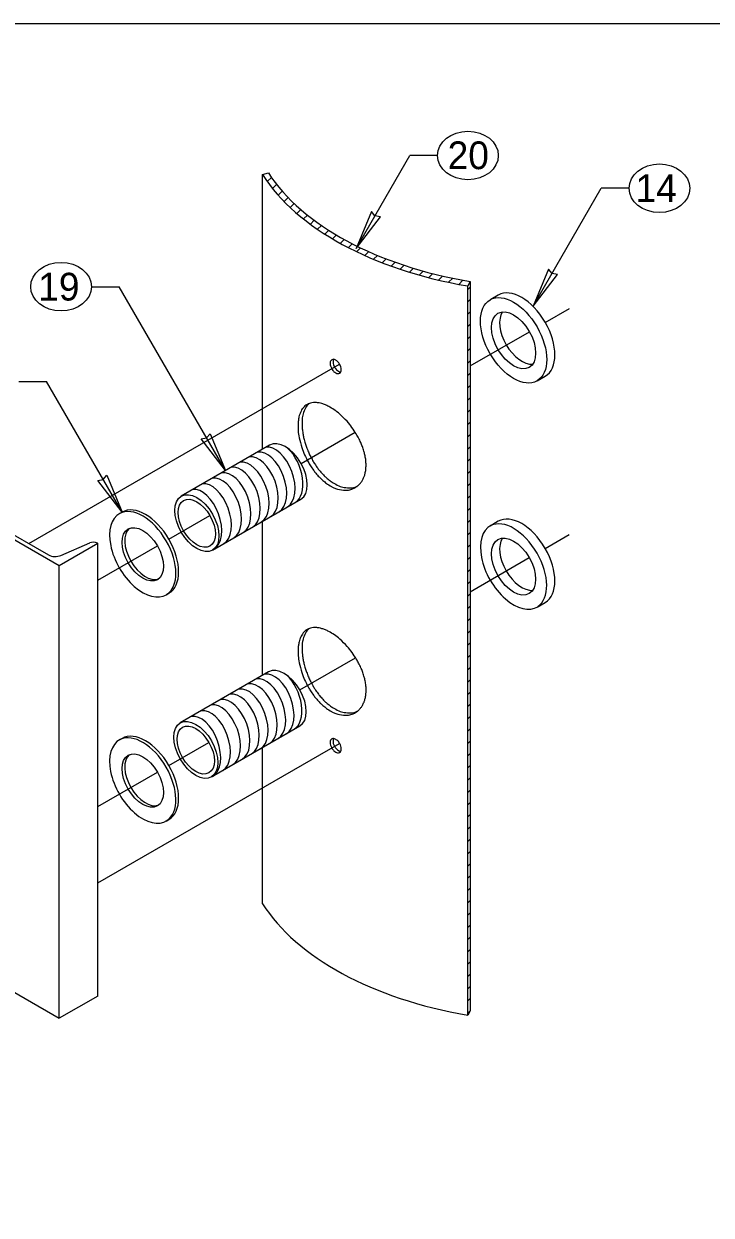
# Model space of a CAD drawing. Extents: x 99862 to 104211, y 98939 to 102076.
# Drawn here: x 102294 to 102690, y 101389 to 102076 of the extents above; entities that cross this region are included whole.
import ezdxf

# ---------------------------------------------------------------- set-up
doc = ezdxf.new("R2010")
doc.units = 0
for name, color, linetype in [('Level 1', 7, 'Continuous'), ('Level 14', 7, 'Continuous'), ('Level 15', 7, 'Continuous'), ('Level 17', 7, 'Continuous'), ('Level 18', 7, 'Continuous'), ('Level 19', 7, 'Continuous'), ('Level 20', 7, 'Continuous')]:
    doc.layers.add(name, color=color, linetype=linetype)

msp = doc.modelspace()

# ---------------------------------------------------------------- linework, layer by layer
at = {"layer": 'Level 1'}
for p, q in [((102431.79, 101988.6), (102435.1, 101989.56)), ((102431.79, 101830.29), (102431.79, 101988.6)), ((102434.49, 101984.6), (102436.85, 101986.97)), ((102437.53, 101980.57), (102439.88, 101982.92)), ((102440.77, 101976.74), (102443.09, 101979.06)), ((102444.17, 101973.08), (102446.48, 101975.38)), ((102447.74, 101969.57), (102450.03, 101971.86)), ((102451.45, 101966.21), (102453.73, 101968.49)), ((102455.31, 101963), (102457.58, 101965.27)), ((102459.33, 101959.95), (102461.59, 101962.21)), ((102463.47, 101957.02), (102465.73, 101959.27)), ((102467.73, 101954.2), (102469.98, 101956.46)), ((102472.09, 101951.49), (102474.34, 101953.75)), ((102476.6, 101948.94), (102478.85, 101951.18)), ((102481.22, 101946.48), (102483.47, 101948.73)), ((102485.94, 101944.13), (102488.19, 101946.38)), ((102490.75, 101941.87), (102493.02, 101944.14)), ((102495.71, 101939.76), (102497.96, 101942.01)), ((102500.76, 101937.73), (102503.02, 101940)), ((102505.89, 101935.8), (102508.18, 101938.09)), ((102511.15, 101933.98), (102513.43, 101936.26)), ((102516.52, 101932.28), (102518.8, 101934.57)), ((102521.98, 101930.67), (102524.29, 101932.98)), ((102527.52, 101929.15), (102529.86, 101931.48)), ((102533.21, 101927.76), (102535.53, 101930.08)), ((102539, 101926.48), (102541.34, 101928.82)), ((102544.88, 101925.29), (102547.26, 101927.67)), ((102551.32, 101926.91), (102549.99, 101924.35)), ((102549.99, 101503.94), (102549.99, 101924.35)), ((102550, 101922.26), (102551.32, 101923.58)), ((102551.32, 101926.91), (102551.32, 101506.5)), ((102550, 101915.19), (102551.32, 101916.51)), ((102550, 101908.12), (102551.32, 101909.44)), ((102550, 101901.05), (102551.32, 101902.37)), ((102550, 101893.98), (102551.32, 101895.3)), ((102471.72, 101881.84), (102471.67, 101881.81)), ((102550, 101886.91), (102551.32, 101888.23)), ((102550, 101879.84), (102551.32, 101881.16)), ((102550, 101872.77), (102551.32, 101874.09)), ((102550, 101865.69), (102551.32, 101867.02)), ((102550, 101858.62), (102551.32, 101859.94)), ((102550, 101851.55), (102551.32, 101852.87)), ((102550, 101844.48), (102551.32, 101845.8)), ((102550, 101837.41), (102551.32, 101838.73)), ((102550, 101830.34), (102551.32, 101831.66)), ((102550, 101823.27), (102551.32, 101824.59)), ((102550, 101816.2), (102551.32, 101817.52)), ((102550, 101809.13), (102551.32, 101810.45)), ((102550, 101802.05), (102551.32, 101803.38)), ((102550, 101794.98), (102551.32, 101796.3)), ((102431.79, 101699.85), (102431.79, 101788.72)), ((102550, 101787.91), (102551.32, 101789.23)), ((102550, 101780.84), (102551.32, 101782.16)), ((102550, 101773.77), (102551.32, 101775.09)), ((102550, 101766.7), (102551.32, 101768.02)), ((102550, 101759.63), (102551.32, 101760.95)), ((102550, 101752.56), (102551.32, 101753.88)), ((102550, 101745.49), (102551.32, 101746.81)), ((102550, 101738.41), (102551.32, 101739.74)), ((102550, 101731.34), (102551.32, 101732.67)), ((102550, 101724.27), (102551.32, 101725.59)), ((102550, 101717.2), (102551.32, 101718.52)), ((102550, 101710.13), (102551.32, 101711.45)), ((102550, 101703.06), (102551.32, 101704.38)), ((102550, 101695.99), (102551.32, 101697.31)), ((102550, 101688.92), (102551.32, 101690.24)), ((102550, 101681.84), (102551.32, 101683.17)), ((102550, 101674.77), (102551.32, 101676.1)), ((102550, 101667.7), (102551.32, 101669.03)), ((102471.72, 101663.22), (102471.67, 101663.19)), ((102550, 101660.63), (102551.32, 101661.95)), ((102431.79, 101568.19), (102431.79, 101658.28)), ((102550, 101653.56), (102551.32, 101654.88)), ((102550, 101646.49), (102551.32, 101647.81)), ((102550, 101639.42), (102551.32, 101640.74)), ((102550, 101632.35), (102551.32, 101633.67)), ((102550, 101625.28), (102551.32, 101626.6)), ((102550, 101618.2), (102551.32, 101619.53)), ((102550, 101611.13), (102551.32, 101612.46)), ((102550, 101604.06), (102551.32, 101605.39)), ((102550, 101596.99), (102551.32, 101598.32)), ((102550, 101589.92), (102551.32, 101591.24)), ((102550, 101582.85), (102551.32, 101584.17)), ((102550, 101575.78), (102551.32, 101577.1)), ((102550, 101568.71), (102551.32, 101570.03)), ((102550, 101561.64), (102551.32, 101562.96)), ((102550, 101554.56), (102551.32, 101555.89)), ((102550, 101547.49), (102551.32, 101548.82)), ((102550, 101540.42), (102551.32, 101541.75)), ((102550, 101533.35), (102551.32, 101534.68)), ((102550, 101526.28), (102551.32, 101527.6)), ((102550, 101519.21), (102551.32, 101520.53)), ((102550, 101512.14), (102551.32, 101513.46)), ((102551.32, 101506.5), (102549.99, 101503.94)), ((102550, 101505.07), (102551.2, 101506.27))]:
    msp.add_line(p, q, dxfattribs=at)
msp.add_lwpolyline([(99862, 99999.5), (103151, 99999.5), (103151, 102075.5), (99862, 102075.5)], close=True, dxfattribs=at)
for centre, major_axis, ratio, start_param, end_param in [((102601.02, 102024.01), (180, 0), 0.57735, 3.489276, 4.425024), ((102601.7, 102025.33), (177.75, 0), 0.57735, 3.497642, 4.425024), ((102429.21, 101808.21), (-6.25, 17.28), 0.565545, 3.242095, 6.183178), ((102434.09, 101811.03), (-6.25, 17.28), 0.565545, 3.242095, 6.183178), ((102438.88, 101813.8), (-6.25, 17.28), 0.565545, 3.242095, 6.183178), ((102443.4, 101816.41), (-6.25, 17.28), 0.565545, 3.242095, 5.457347), ((102418.82, 101802.22), (-6.25, 17.28), 0.565545, 3.242095, 6.183178), ((102423.93, 101805.17), (-6.25, 17.28), 0.565545, 3.242095, 6.183178), ((102408.03, 101795.99), (-6.25, 17.28), 0.565545, 3.242095, 6.183178), ((102413.44, 101799.11), (-6.25, 17.28), 0.565545, 3.242095, 6.183178), ((102396.63, 101789.41), (-6.25, 17.28), 0.565545, 3.242095, 6.183178), ((102402.22, 101792.63), (-6.25, 17.28), 0.565545, 3.242095, 6.183178), ((102433.5, 101680.25), (-6.25, 17.28), 0.565545, 3.242095, 6.183178), ((102438.29, 101683.02), (-6.25, 17.28), 0.565545, 3.242095, 6.183178), ((102442.81, 101685.63), (-6.25, 17.28), 0.565545, 3.242095, 5.457347), ((102418.24, 101671.44), (-6.25, 17.28), 0.565545, 3.242095, 6.183178), ((102423.34, 101674.39), (-6.25, 17.28), 0.565545, 3.242095, 6.183178), ((102428.62, 101677.44), (-6.25, 17.28), 0.565545, 3.242095, 6.183178), ((102407.45, 101665.21), (-6.25, 17.28), 0.565545, 3.242095, 6.183178), ((102412.85, 101668.33), (-6.25, 17.28), 0.565545, 3.242095, 6.183178), ((102396.04, 101658.63), (-6.25, 17.28), 0.565545, 3.242095, 6.183178), ((102401.63, 101661.85), (-6.25, 17.28), 0.565545, 3.242095, 6.183178), ((102601.02, 101603.6), (-180, 0), 0.57735, 0.347684, 1.283395)]:
    msp.add_ellipse(centre, major_axis=major_axis, ratio=ratio, start_param=start_param, end_param=end_param, dxfattribs=at)
for points, degree in [([(102473.9, 101874.23), (102473.06, 101874.71), (102472.24, 101875.59), (102471.09, 101877.64), (102470.75, 101878.8), (102470.75, 101880.72), (102471.08, 101881.47), (102472.25, 101882.15), (102473.07, 101882.06), (102474.73, 101881.1), (102475.57, 101880.23), (102476.77, 101878.21), (102477.12, 101877.07), (102477.13, 101875.13), (102476.77, 101874.37), (102475.57, 101873.67), (102474.74, 101873.74), (102473.9, 101874.23)], 3), ([(102472.61, 101882.01), (102472.42, 101881.6), (102472.32, 101881.08), (102472.39, 101879.51), (102472.76, 101878.36), (102473.98, 101876.32), (102474.82, 101875.49), (102476.05, 101874.85), (102476.45, 101874.74), (102476.83, 101874.73)], 3), ([(102470.75, 101809.17), (102469.46, 101809.92), (102468.2, 101810.8), (102465.74, 101812.85), (102464.54, 101814.03), (102462.26, 101816.58), (102461.2, 101817.96), (102459.19, 101820.9), (102458.25, 101822.47), (102455.75, 101827.27), (102454.42, 101830.71), (102452.66, 101837.39), (102452.2, 101840.69), (102452.2, 101845.12), (102452.32, 101846.53), (102452.76, 101849.11), (102453.1, 101850.29), (102453.98, 101852.4), (102454.54, 101853.34), (102455.83, 101854.9), (102456.57, 101855.53), (102458.26, 101856.51), (102459.18, 101856.84), (102461.18, 101857.18), (102462.26, 101857.19), (102464.54, 101856.9), (102465.72, 101856.61), (102468.18, 101855.71), (102469.47, 101855.1), (102473.31, 101852.89), (102475.94, 101850.85), (102480.85, 101845.99), (102483.17, 101843.13), (102486.09, 101838.56), (102486.98, 101836.97), (102488.53, 101833.77), (102489.19, 101832.16), (102490.28, 101828.91), (102490.69, 101827.28), (102491.25, 101824.13), (102491.39, 101822.6), (102491.39, 101819.61), (102491.25, 101818.2), (102490.7, 101815.57), (102490.29, 101814.33), (102489.21, 101812.1), (102488.55, 101811.12), (102487.01, 101809.4), (102486.11, 101808.68), (102483.2, 101806.99), (102480.88, 101806.49), (102475.98, 101806.83), (102473.34, 101807.68), (102470.75, 101809.17)], 3), ([(102458.64, 101856.59), (102457.43, 101855.6), (102456.46, 101854.21), (102454.92, 101850.37), (102454.49, 101847.7), (102454.53, 101843.25), (102454.66, 101841.66), (102455.13, 101838.43), (102455.48, 101836.78), (102456.39, 101833.42), (102456.95, 101831.71), (102458.27, 101828.38), (102459.02, 101826.74), (102460.73, 101823.5), (102461.66, 101821.97), (102463.67, 101819.06), (102464.77, 101817.67), (102467.06, 101815.14), (102468.25, 101814), (102470.71, 101811.98), (102472, 101811.09), (102475.84, 101808.93), (102478.48, 101808.11), (102482.82, 101807.87), (102484.63, 101808.17), (102486.24, 101808.85)], 3), ([(102470.79, 101679.42), (102469.5, 101680.16), (102468.24, 101681.05), (102465.78, 101683.1), (102464.58, 101684.27), (102462.3, 101686.83), (102461.23, 101688.2), (102459.23, 101691.14), (102458.29, 101692.72), (102455.79, 101697.52), (102454.46, 101700.96), (102452.7, 101707.63), (102452.24, 101710.94), (102452.24, 101715.36), (102452.35, 101716.78), (102452.8, 101719.36), (102453.13, 101720.53), (102454.02, 101722.65), (102454.57, 101723.58), (102455.87, 101725.14), (102456.61, 101725.78), (102458.3, 101726.76), (102459.22, 101727.08), (102461.22, 101727.42), (102462.3, 101727.44), (102464.58, 101727.15), (102465.76, 101726.85), (102468.22, 101725.96), (102469.51, 101725.35), (102473.35, 101723.14), (102475.98, 101721.09), (102480.89, 101716.24), (102483.21, 101713.38), (102486.13, 101708.81), (102487.02, 101707.21), (102488.57, 101704.01), (102489.23, 101702.4), (102490.32, 101699.16), (102490.73, 101697.52), (102491.29, 101694.38), (102491.43, 101692.84), (102491.43, 101689.86), (102491.29, 101688.45), (102490.74, 101685.82), (102490.33, 101684.58), (102489.25, 101682.35), (102488.59, 101681.36), (102487.04, 101679.65), (102486.15, 101678.92), (102483.24, 101677.24), (102480.92, 101676.73), (102476.01, 101677.08), (102473.38, 101677.92), (102470.79, 101679.42)], 3), ([(102458.67, 101726.84), (102457.47, 101725.84), (102456.5, 101724.45), (102454.96, 101720.62), (102454.53, 101717.95), (102454.57, 101713.49), (102454.7, 101711.91), (102455.17, 101708.68), (102455.52, 101707.03), (102456.43, 101703.67), (102456.99, 101701.96), (102458.31, 101698.62), (102459.06, 101696.98), (102460.77, 101693.75), (102461.7, 101692.22), (102463.71, 101689.3), (102464.81, 101687.91), (102467.1, 101685.38), (102468.28, 101684.25), (102470.75, 101682.22), (102472.04, 101681.33), (102475.88, 101679.18), (102478.52, 101678.36), (102482.86, 101678.12), (102484.67, 101678.42), (102486.28, 101679.1)], 3), ([(102473.9, 101655.61), (102473.06, 101656.1), (102472.24, 101656.98), (102471.09, 101659.02), (102470.75, 101660.18), (102470.75, 101662.1), (102471.08, 101662.86), (102472.25, 101663.53), (102473.07, 101663.44), (102474.73, 101662.48), (102475.57, 101661.61), (102476.77, 101659.59), (102477.12, 101658.45), (102477.13, 101656.51), (102476.77, 101655.75), (102475.57, 101655.06), (102474.74, 101655.13), (102473.9, 101655.61)], 3), ([(102472.61, 101663.39), (102472.44, 101663.03), (102472.34, 101662.58), (102472.34, 101661.1), (102472.68, 101659.94), (102473.83, 101657.9), (102474.65, 101657.02), (102475.49, 101656.53)], 3), ([(102475.49, 101656.53), (102475.95, 101656.27), (102476.41, 101656.13), (102476.82, 101656.11)], 2)]:
    msp.add_open_spline(points, degree=degree, dxfattribs=at)
at = {"layer": 'Level 14'}
for p, q in [((102563.3, 101916.61), (102562.91, 101916.38)), ((102567.59, 101919.08), (102563.3, 101916.61)), ((102589.91, 101869.61), (102594.59, 101872.32)), ((102567.59, 101788.65), (102562.91, 101785.94)), ((102589.91, 101739.18), (102594.59, 101741.88))]:
    msp.add_line(p, q, dxfattribs=at)
for centre, major_axis, start_param, end_param in [((102581.09, 101895.7), (-13.5, 23.38), 3.141593, 6.283185), ((102581.09, 101895.7), (9, -15.59), 3.404941, 4.713019), ((102581.09, 101895.7), (9, -15.59), 4.713019, 6.019837), ((102576.41, 101762.56), (-13.5, 23.38), 6.251087, 9.456261), ((102576.41, 101762.56), (-13.5, 23.38), 3.175146, 6.249339), ((102581.09, 101765.27), (-13.5, 23.38), 3.141593, 6.283185), ((102581.09, 101765.27), (9, -15.59), 3.404941, 4.712389), ((102581.09, 101765.27), (9, -15.59), 4.712389, 6.019837)]:
    msp.add_ellipse(centre, major_axis=major_axis, ratio=0.57735, start_param=start_param, end_param=end_param, dxfattribs=at)
for centre, major_axis in [((102576.41, 101893), (-13.5, 23.38)), ((102576.41, 101893), (9, -15.59)), ((102576.41, 101762.56), (9, -15.59))]:
    msp.add_ellipse(centre, major_axis=major_axis, ratio=0.57735, dxfattribs=at)
at = {"layer": 'Level 15'}
for p, q in [((102485.64, 101945.94), (102516.61, 101999.58)), ((102532.61, 101999.58), (102516.61, 101999.58)), ((102587.72, 101912.69), (102626.98, 101980.7)), ((102642.98, 101980.7), (102626.98, 101980.7)), ((102333.14, 101923.94), (102349.14, 101923.94)), ((102410.36, 101817.91), (102349.14, 101923.94)), ((102594.71, 101903.29), (102608.57, 101911.29)), ((102551.32, 101878.24), (102585.52, 101897.98)), ((102297.11, 101775.83), (102476.17, 101879.22)), ((102291.28, 101869.3), (102307.28, 101869.3)), ((102350.8, 101793.92), (102307.28, 101869.3)), ((102453.93, 101822.01), (102485.15, 101840.04)), ((102377.8, 101778.32), (102401.42, 101791.96)), ((102594.59, 101773.06), (102608.45, 101781.06)), ((102336.88, 101754.7), (102371.15, 101774.48)), ((102551.32, 101748.08), (102585.41, 101767.76)), ((102453.23, 101691.44), (102485.37, 101710)), ((102336.88, 101580.18), (102476.17, 101660.6)), ((102377.8, 101647.9), (102400.83, 101661.19)), ((102336.88, 101624.27), (102371.15, 101644.05))]:
    msp.add_line(p, q, dxfattribs=at)
for points in [[(102485.64, 101945.94), (102499.64, 101964.22), (102496.52, 101964.8), (102494.47, 101967.21)], [(102587.72, 101912.69), (102601.72, 101930.97), (102598.61, 101931.55), (102596.55, 101933.96)], [(102410.36, 101817.91), (102396.36, 101836.18), (102399.47, 101836.76), (102401.53, 101839.17)]]:
    msp.add_lwpolyline(points, close=True, dxfattribs=at)
at = {"layer": 'Level 17'}
for p, q in [((102350.8, 101793.92), (102349.21, 101793)), ((102376.21, 101746.24), (102377.8, 101747.15)), ((102350.8, 101663.48), (102349.21, 101662.57)), ((102376.21, 101615.8), (102377.8, 101616.72))]:
    msp.add_line(p, q, dxfattribs=at)
msp.add_lwpolyline([(102350.8, 101793.92), (102336.8, 101812.2), (102339.91, 101812.78), (102341.97, 101815.18)], close=True, dxfattribs=at)
for centre, major_axis, start_param, end_param in [((102362.71, 101769.62), (-13.5, 23.38), 6.266721, 9.43803), ((102362.71, 101769.62), (-13.5, 23.38), 3.161499, 6.264759), ((102364.3, 101770.54), (-13.5, 23.38), 3.141593, 6.283185), ((102364.3, 101770.54), (8.44, -14.61), 3.236014, 4.712769), ((102364.3, 101770.54), (8.44, -14.61), 4.712769, 6.188764), ((102362.71, 101639.18), (-13.5, 23.38), 6.252276, 9.459342), ((102362.71, 101639.18), (-13.5, 23.38), 3.177639, 6.246215), ((102364.3, 101640.1), (-13.5, 23.38), 3.141593, 6.283185), ((102364.3, 101640.1), (8.44, -14.61), 3.236014, 4.712389), ((102364.3, 101640.1), (8.44, -14.61), 4.712389, 6.188764)]:
    msp.add_ellipse(centre, major_axis=major_axis, ratio=0.57735, start_param=start_param, end_param=end_param, dxfattribs=at)
for centre in [(102362.71, 101769.62), (102362.71, 101639.18)]:
    msp.add_ellipse(centre, major_axis=(8.44, -14.61), ratio=0.57735, dxfattribs=at)
at = {"layer": 'Level 18'}
for p, q in [((102435.82, 101832.6), (102384.91, 101803.21)), ((102402.91, 101772.03), (102453.82, 101801.43)), ((102435.23, 101701.83), (102384.32, 101672.43)), ((102402.32, 101641.26), (102453.23, 101670.65))]:
    msp.add_line(p, q, dxfattribs=at)
for centre in [(102444.82, 101817.01), (102444.23, 101686.24)]:
    msp.add_ellipse(centre, major_axis=(-9, 15.59), ratio=0.57735, start_param=3.141593, end_param=6.283185, dxfattribs=at)
for centre, major_axis in [((102393.91, 101787.62), (-9, 15.59)), ((102393.84, 101787.55), (7.59, -13.15)), ((102393.32, 101656.85), (-9, 15.59)), ((102393.25, 101656.78), (7.59, -13.15))]:
    msp.add_ellipse(centre, major_axis=major_axis, ratio=0.57735, dxfattribs=at)
at = {"layer": 'Level 19'}
for p, q in [((102314.61, 101762.97), (102238.24, 101807.06)), ((102336.88, 101775.83), (102314.61, 101762.97)), ((102336.88, 101514.96), (102336.88, 101775.83)), ((102314.61, 101502.1), (102314.61, 101762.97)), ((102250.27, 101539.25), (102314.61, 101502.1)), ((102336.88, 101514.96), (102314.61, 101502.1))]:
    msp.add_line(p, q, dxfattribs=at)
at = {"layer": 'Level 20'}
for p, q in [((102249.17, 101803.51), (102308.45, 101769.28)), ((102315.51, 101768.99), (102332.16, 101776.19)), ((102336.57, 101776.01), (102336.88, 101775.83))]:
    msp.add_line(p, q, dxfattribs=at)
for centre in [(102550.11, 101999.58), (102660.48, 101980.7), (102315.64, 101923.94)]:
    msp.add_ellipse(centre, major_axis=(-17.5, 0), ratio=0.8, dxfattribs=at)
for centre, major_axis in [((102334.18, 101774.63), (3.38, 0)), ((102312.27, 101771.49), (-5.4, 0))]:
    msp.add_ellipse(centre, major_axis=major_axis, ratio=0.57735, start_param=0.785398, end_param=2.213633, dxfattribs=at)

# ---------------------------------------------------------------- texts
for s, p in [('20', (102538.41, 101991.71)), ('14', (102646.7, 101972.7)), ('19', (102302.48, 101915.95))]:
    msp.add_text(s, height=16, dxfattribs=at).set_placement(p)

doc.saveas('drawing.dxf')
